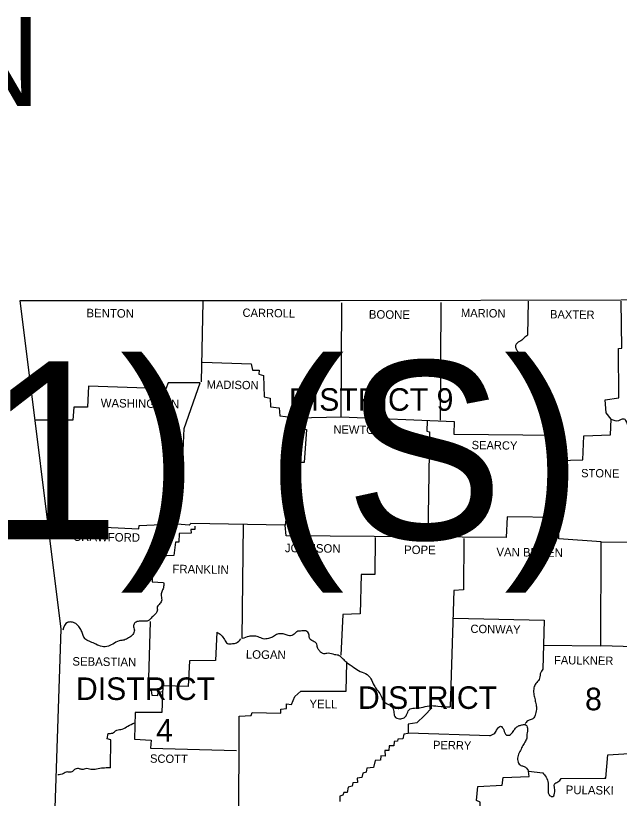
# Model space of a CAD drawing. Extents: x 8749 to 11879, y 13275 to 15339.
# Drawn here: x 11180.1 to 11484.9, y 14906.6 to 15302.2 of the extents above; entities that cross this region are included whole.
import ezdxf

# ---------------------------------------------------------------- set-up
doc = ezdxf.new("R2010")
doc.units = 0
doc.layers.add('R_Draft', color=7, linetype='Continuous')

msp = doc.modelspace()

# ---------------------------------------------------------------- linework, layer by layer
at = {"layer": 'R_Draft'}
for points in [[(11182.34, 15158.28), (11344.04, 15158.18), (11485.94, 15158.48), (11653.34, 15161.08), (11730.94, 15162.88)], [(11194.04, 14720.78), (11203.04, 14992.08), (11182.34, 15158.28)], [(11274.64, 15157.68), (11273.74, 15117.18)], [(11438.84, 15157.88), (11438.64, 15140.78)], [(11455.64, 14916.58), (11478.14, 14916.68), (11479.14, 14928.48), (11492.54, 14929.48), (11492.54, 14983.08), (11475.54, 14983.58), (11475.84, 15036.28), (11454.44, 15037.68), (11454.14, 15061.28), (11453.44, 15062.48), (11454.04, 15077.28), (11466.44, 15077.68), (11466.94, 15089.88), (11480.54, 15090.38), (11480.74, 15098.28), (11478.34, 15101.38), (11477.74, 15108.08), (11484.74, 15109.08), (11484.44, 15133.98), (11486.14, 15134.08), (11485.94, 15157.88)], [(11274.44, 15127.08), (11299.04, 15126.28), (11299.64, 15123.08), (11303.04, 15122.98), (11302.94, 15120.98), (11305.34, 15120.38), (11305.54, 15109.48), (11308.64, 15108.78), (11308.84, 15104.48), (11313.24, 15103.88), (11313.44, 15099.88), (11322.14, 15098.98), (11344.54, 15099.48), (11344.74, 15156.98)], [(11394.84, 15157.18), (11394.54, 15097.78)], [(11316.74, 15039.28), (11316.24, 15044.58), (11268.54, 15045.48), (11267.64, 15044.58), (11261.74, 15045.08), (11262.34, 15056.28), (11263.54, 15056.38), (11265.14, 15093.48), (11273.24, 15116.68), (11257.14, 15116.58), (11255.94, 15113.58), (11216.94, 15114.98), (11216.34, 15104.28), (11209.44, 15104.28), (11208.94, 15097.68), (11190.24, 15097.78)], [(11321.94, 15098.78), (11322.34, 15093.38), (11326.94, 15093.08), (11325.74, 15076.28), (11323.64, 15076.38), (11323.24, 15073.68), (11320.84, 15073.68), (11320.74, 15069.08), (11319.24, 15068.98), (11318.74, 15063.08), (11316.54, 15062.78), (11316.24, 15053.78), (11317.24, 15053.08), (11316.24, 15044.58)], [(11344.54, 15099.48), (11401.54, 15097.08), (11401.44, 15090.58), (11453.74, 15090.18)], [(11454.04, 15077.28), (11453.94, 15099.78)], [(11387.84, 15097.38), (11387.74, 15092.18), (11389.04, 15091.88), (11388.24, 15039.08)], [(11454.04, 15048.58), (11428.24, 15048.88), (11427.74, 15038.38), (11316.74, 15039.28)], [(11196.84, 15044.98), (11242.34, 15042.88), (11242.54, 15044.48), (11261.54, 15045.38)], [(11270.54, 15044.18), (11270.54, 15042.38), (11268.64, 15042.38), (11268.74, 15040.58), (11262.64, 15040.48), (11262.54, 15035.98), (11260.84, 15035.98), (11259.94, 15029.28), (11249.14, 15028.78), (11249.04, 15016.08), (11254.84, 15015.68)], [(11294.54, 14987.28), (11295.24, 15044.98)], [(11361.64, 15038.48), (11361.54, 15019.78), (11354.64, 15019.68), (11354.04, 14999.78), (11345.24, 14999.48), (11344.24, 14978.88)], [(11406.44, 15037.98), (11406.24, 15011.98), (11401.44, 15011.58), (11399.54, 14952.78)], [(11475.84, 15036.28), (11527.24, 15035.98), (11531.64, 15038.08), (11531.34, 14998.98), (11528.34, 14997.68), (11525.64, 14995.38), (11524.74, 14994.48), (11524.64, 14983.28), (11491.94, 14983.28)], [(11248.04, 14995.88), (11247.04, 14961.48), (11248.54, 14961.08), (11248.84, 14958.68), (11251.84, 14958.48), (11252.14, 14960.18), (11254.54, 14960.58)], [(11401.24, 14997.68), (11446.94, 14996.58), (11446.34, 14971.88)], [(11281.64, 14990.48), (11280.94, 14976.18), (11267.94, 14976.08), (11267.24, 14963.08), (11254.34, 14963.38), (11253.94, 14949.98), (11240.44, 14949.88), (11240.04, 14936.48), (11248.54, 14935.98), (11248.24, 14931.88), (11291.64, 14930.68)], [(11446.44, 14983.98), (11475.54, 14983.58)], [(11292.84, 14889.68), (11293.04, 14948.18), (11299.04, 14948.38), (11299.54, 14949.98), (11314.04, 14949.58), (11313.94, 14951.68), (11316.84, 14951.98), (11316.94, 14954.28), (11319.44, 14954.08), (11321.14, 14958.08), (11324.14, 14960.68), (11346.94, 14960.78), (11347.34, 14975.18)], [(11390.24, 14952.38), (11386.64, 14948.48), (11382.74, 14944.78), (11378.24, 14944.08), (11378.24, 14939.38), (11376.04, 14939.08), (11375.64, 14936.68), (11373.14, 14936.48), (11372.94, 14935.38), (11371.24, 14935.28), (11371.14, 14933.18), (11368.74, 14933.08), (11368.54, 14930.68), (11366.54, 14930.68), (11366.64, 14927.88), (11364.44, 14928.08), (11364.34, 14925.88), (11361.64, 14925.68), (11360.84, 14922.08), (11357.44, 14921.78), (11357.14, 14919.78), (11355.34, 14919.28), (11354.84, 14917.18), (11352.54, 14916.68), (11352.74, 14914.58), (11350.44, 14914.38), (11350.04, 14912.78), (11347.94, 14912.18), (11347.44, 14909.48), (11345.84, 14909.58), (11345.34, 14908.18), (11343.84, 14907.68), (11343.74, 14904.98)], [(11227.94, 14921.98), (11228.24, 14936.08), (11226.24, 14936.68), (11226.84, 14939.38)], [(11419.54, 14938.18), (11378.34, 14939.48)], [(11414.64, 14899.98), (11414.64, 14904.58), (11412.84, 14905.48), (11413.54, 14912.48), (11425.84, 14913.18), (11426.24, 14917.08), (11439.34, 14917.58), (11439.04, 14920.28), (11446.24, 14919.48)], [(11477.64, 14916.78), (11478.14, 14917.28)]]:
    msp.add_lwpolyline(points, dxfattribs=at)
for points in [[(11438.64, 15140.78), (11436.84, 15139.28), (11435.24, 15137.88), (11432.84, 15136.18), (11432.54, 15134.58), (11433.34, 15132.98), (11434.14, 15131.68), (11434.44, 15129.88), (11435.14, 15128.38), (11436.84, 15127.78), (11438.24, 15126.48), (11438.74, 15124.68), (11438.94, 15122.98), (11440.54, 15122.18), (11442.34, 15121.58), (11444.04, 15120.38), (11444.84, 15118.88), (11445.04, 15116.98), (11445.74, 15115.48), (11446.54, 15113.68), (11446.74, 15112.18), (11446.54, 15110.68), (11446.94, 15109.28), (11448.24, 15107.88), (11450.54, 15107.18), (11452.14, 15106.18), (11453.24, 15104.78), (11452.54, 15103.08), (11452.64, 15101.58), (11453.54, 15099.78)], [(11480.74, 15098.28), (11484.74, 15097.58), (11487.14, 15098.48), (11488.84, 15095.88), (11489.74, 15093.88), (11491.24, 15090.98), (11493.64, 15090.08), (11495.44, 15088.48), (11495.44, 15086.78), (11493.84, 15085.18), (11492.64, 15083.58), (11493.04, 15081.68), (11493.44, 15079.08), (11493.44, 15076.58), (11492.84, 15074.28), (11492.34, 15072.18), (11492.84, 15070.38), (11494.74, 15070.68), (11496.74, 15072.18), (11498.84, 15072.18), (11500.84, 15071.08), (11502.94, 15069.18), (11505.04, 15069.58), (11506.74, 15070.08), (11509.14, 15070.78), (11510.84, 15069.88), (11512.34, 15068.68), (11514.14, 15066.78), (11515.84, 15065.58), (11518.04, 15064.48), (11520.74, 15063.78), (11523.24, 15062.08), (11523.64, 15059.18), (11523.54, 15056.68), (11523.34, 15053.58), (11523.14, 15050.18), (11523.44, 15046.88), (11524.54, 15044.68), (11525.94, 15042.08), (11526.34, 15039.68), (11526.24, 15035.88)], [(11254.84, 15015.68), (11254.84, 15013.58), (11254.04, 15011.38), (11253.54, 15009.48), (11253.84, 15006.98), (11252.94, 15004.98), (11251.64, 15003.38), (11251.64, 15001.38), (11250.14, 14999.28), (11248.54, 14997.68), (11247.14, 14996.38), (11244.64, 14996.18), (11242.54, 14996.08), (11240.44, 14995.38), (11239.64, 14993.88), (11240.04, 14991.58), (11239.24, 14989.38), (11237.14, 14987.68), (11234.84, 14986.58), (11232.44, 14986.18), (11229.14, 14984.58), (11226.14, 14983.28), (11222.94, 14983.48), (11219.94, 14984.78), (11217.24, 14985.98), (11215.14, 14987.18), (11213.44, 14990.88), (11212.34, 14992.88), (11210.44, 14994.88), (11208.14, 14995.68), (11206.24, 14995.48), (11203.94, 14991.58)], [(11347.34, 14975.18), (11345.44, 14976.98), (11343.44, 14978.68), (11341.24, 14979.18), (11337.84, 14979.88), (11335.64, 14979.68), (11334.34, 14980.28), (11333.44, 14981.28), (11332.54, 14982.78), (11332.04, 14984.88), (11330.34, 14985.98), (11328.44, 14987.68), (11328.14, 14989.48), (11326.64, 14991.18), (11324.54, 14991.18), (11322.14, 14990.78), (11320.74, 14989.48), (11318.34, 14988.78), (11316.14, 14989.38), (11314.04, 14989.78), (11311.84, 14989.38), (11309.84, 14988.08), (11307.84, 14987.38), (11305.14, 14987.18), (11302.64, 14988.18), (11300.24, 14988.58), (11297.84, 14988.38), (11294.54, 14987.28)], [(11281.64, 14990.48), (11283.84, 14989.08), (11285.54, 14986.78), (11287.04, 14984.88), (11289.54, 14984.78), (11291.54, 14985.18), (11293.84, 14987.18)], [(11347.34, 14975.18), (11350.84, 14972.78), (11354.14, 14970.68), (11357.54, 14969.18), (11359.44, 14966.98), (11361.14, 14963.58), (11362.54, 14961.48), (11364.34, 14958.88), (11365.64, 14955.98), (11367.74, 14954.38), (11369.94, 14952.98), (11371.04, 14950.48), (11371.54, 14947.98), (11373.94, 14946.78), (11376.24, 14947.28), (11377.54, 14948.78), (11378.74, 14951.38), (11381.44, 14952.18), (11384.94, 14952.48), (11388.94, 14953.38), (11393.34, 14953.18), (11399.54, 14952.78)], [(11446.34, 14971.88), (11445.04, 14969.58), (11444.44, 14966.58), (11442.84, 14964.68), (11441.84, 14962.48), (11441.74, 14959.58), (11442.24, 14956.98), (11442.74, 14954.48), (11443.14, 14952.18), (11442.64, 14949.28), (11441.34, 14946.78), (11439.34, 14946.08), (11437.44, 14944.38)], [(11226.84, 14939.38), (11229.04, 14939.58), (11231.14, 14940.98), (11233.94, 14941.58), (11236.74, 14943.08), (11240.24, 14944.68)], [(11419.54, 14938.18), (11422.04, 14939.58), (11423.34, 14941.68), (11424.94, 14942.98), (11426.54, 14941.18), (11427.94, 14938.58), (11429.44, 14938.58), (11431.34, 14940.38), (11432.54, 14941.98), (11434.04, 14943.18), (11435.64, 14943.68), (11437.34, 14943.88), (11438.64, 14941.98), (11438.24, 14938.98), (11438.24, 14936.98), (11437.14, 14934.88), (11435.94, 14932.68), (11434.64, 14930.18), (11433.64, 14927.48), (11433.84, 14924.88), (11435.24, 14923.18), (11436.84, 14922.68), (11439.04, 14920.48)], [(11227.94, 14921.98), (11225.04, 14921.88), (11221.74, 14921.48), (11218.74, 14921.08), (11216.04, 14921.58), (11213.54, 14921.18), (11211.84, 14921.58), (11209.74, 14921.08), (11208.54, 14919.88), (11206.04, 14919.88), (11204.24, 14919.08), (11201.34, 14918.38)], [(11446.24, 14919.48), (11447.94, 14917.28), (11448.94, 14914.28), (11448.94, 14910.88), (11449.74, 14908.08), (11451.34, 14907.48), (11452.34, 14909.88), (11452.14, 14912.28), (11452.14, 14913.68), (11453.84, 14914.88), (11455.64, 14916.58)]]:
    msp.add_spline(points, degree=3, dxfattribs=at)

# ---------------------------------------------------------------- texts
for s, height, p in [('ARKANSAS DEPARTMENT OF TRANSPORTATION ', 45, (9761.64, 15256.54)), ('I-30 STR. & APPRS. (HWY. 51) (S)', 90, (9574.11, 15037.53)), ('DISTRICT 9', 11.4, (11318.14, 15102.48)), ('DISTRICT', 11.4, (11210.54, 14956.28)), ('DISTRICT', 11.4, (11352.94, 14951.78)), ('8', 11.4, (11467.64, 14951.08)), ('4', 11.4, (11251.04, 14935.28))]:
    msp.add_text(s, height=height, dxfattribs=at).set_placement(p)
for s, height, rotation, p in [('BENTON', 4.301, 359.2527, (11215.84, 15149.78)), ('CARROLL', 4.201, 359.1481, (11294.64, 15149.98)), ('MARION', 4.201, 359.1854, (11404.94, 15149.88)), ('BOONE', 4.301, 359.4001, (11358.44, 15149.08)), ('BAXTER', 4.201, 359.2559, (11449.94, 15149.18)), ('MADISON', 4.201, 359.0906, (11276.54, 15113.68)), ('WASHINGTON', 4.3, 359.232, (11223.04, 15104.28)), ('NEWTON', 4.201, 359.2717, (11340.54, 15090.98)), ('SEARCY', 4.199, 359.2527, (11410.34, 15083.08)), ('STONE', 4.199, 359.4001, (11465.64, 15068.88)), ('CRAWFORD', 4.3, 359.2771, (11209.04, 15036.68)), ('JOHNSON', 4.301, 359.3514, (11316.04, 15030.98)), ('POPE', 4.301, 359.6155, (11376.24, 15030.08)), ('VAN BUREN', 4.301, 359.3508, (11422.84, 15028.98)), ('FRANKLIN', 4.301, 359.1815, (11259.24, 15020.38)), ('CONWAY', 4.199, 359.0371, (11409.74, 14990.18)), ('LOGAN', 4.301, 359.3969, (11296.34, 14977.18)), ('SEBASTIAN', 4.3, 359.2816, (11208.74, 14973.68)), ('FAULKNER', 4.201, 359.2486, (11451.94, 14974.38)), ('YELL', 4.301, 359.1987, (11328.44, 14952.18)), ('PERRY', 4.201, 359.0858, (11390.84, 14931.48)), ('SCOTT', 4.201, 359.4063, (11247.94, 14924.58)), ('PULASKI', 4.301, 359.053, (11457.84, 14908.78))]:
    msp.add_text(s, height=height, rotation=rotation, dxfattribs=at).set_placement(p)

doc.saveas('drawing.dxf')
